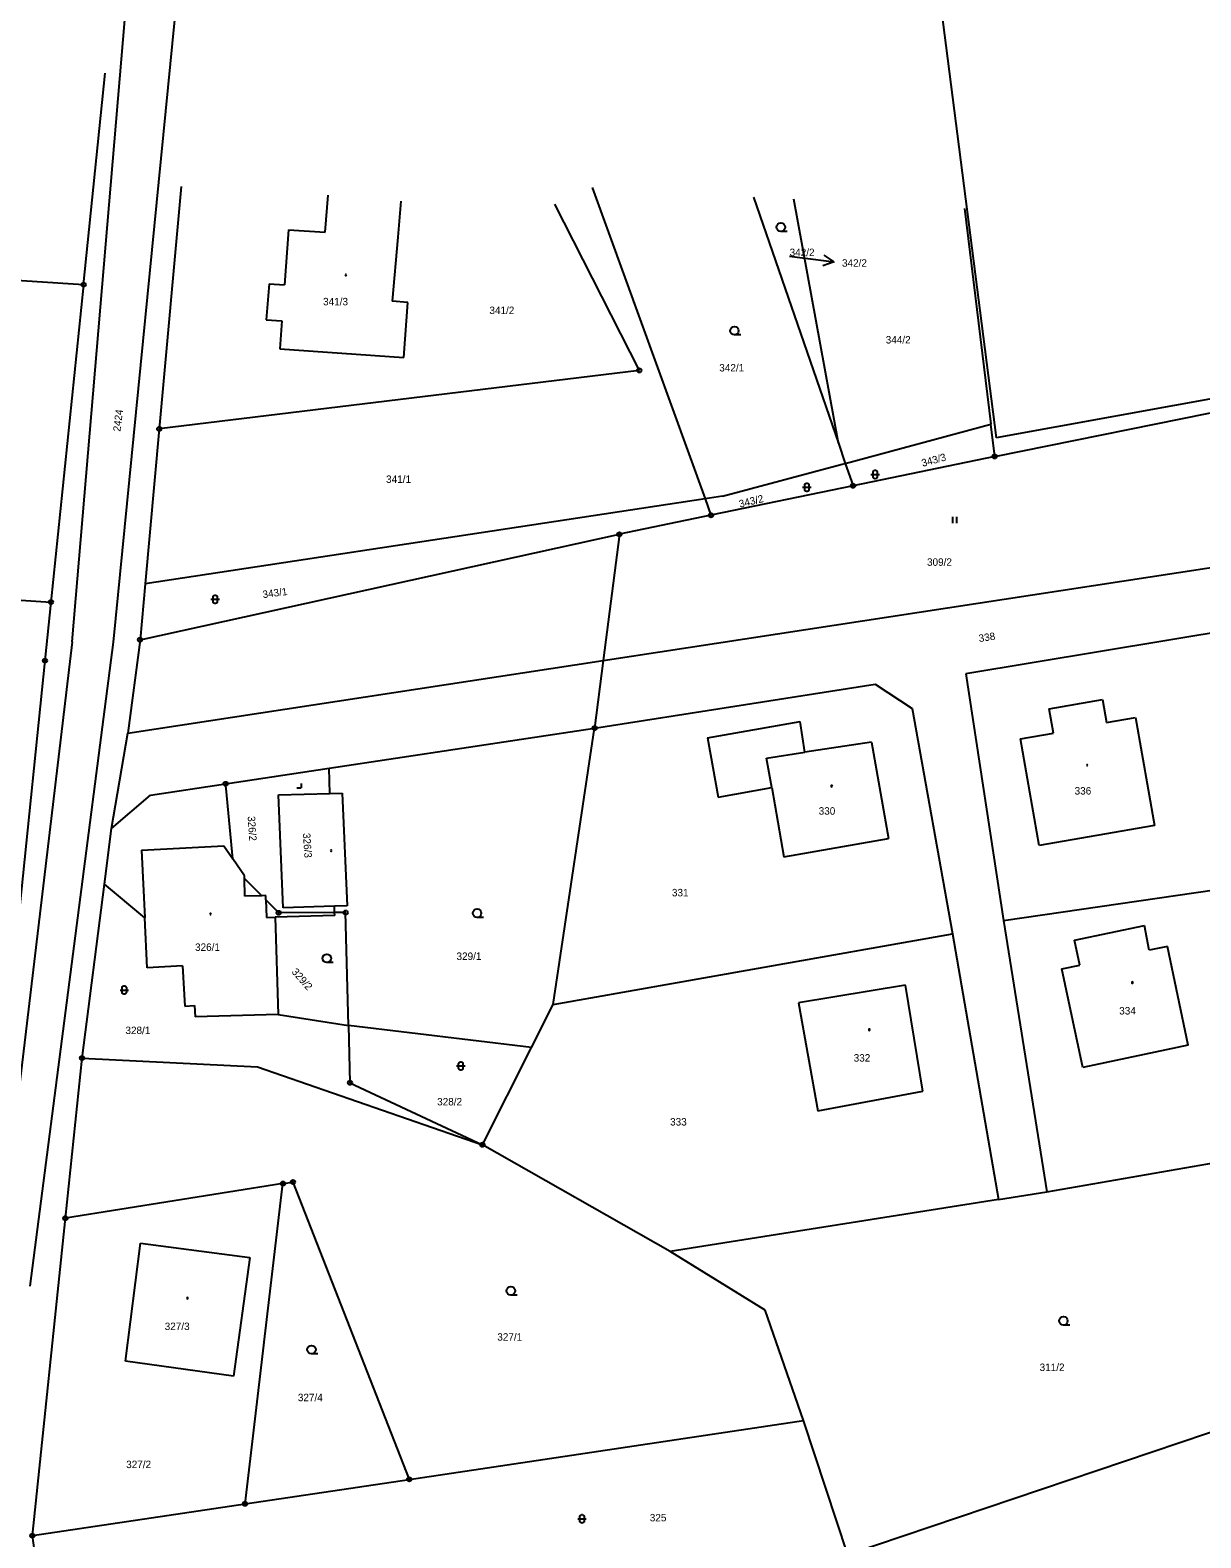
# Model space of a CAD drawing. Extents: x -454285 to -453563, y -1108687 to -1108249.
# Drawn here: x -454136.3 to -454026.3, y -1108463.6 to -1108321.8 of the extents above; entities that cross this region are included whole.
import ezdxf

# ---------------------------------------------------------------- set-up
doc = ezdxf.new("R2010")
doc.units = 0
for name, color, linetype in [('1', 7, 'Continuous'), ('13', 7, 'Continuous'), ('14', 7, 'Continuous'), ('15', 7, 'Continuous'), ('16', 7, 'Continuous'), ('2', 7, 'Continuous'), ('23', 7, 'Continuous'), ('25', 7, 'Continuous'), ('28', 7, 'Continuous')]:
    doc.layers.add(name, color=color, linetype=linetype)

# ---------------------------------------------------------------- blocks, each defined once
blk = doc.blocks.new('Z402')
for start, end in [(0, 180), (180, 0)]:
    blk.add_arc((0, 0), 0.15, start, end)
blk = doc.blocks.new('Z105')
for radius in [0.5, 0.01]:
    blk.add_circle((0, 0), radius)
blk = doc.blocks.new('Z3060')
for p, q in [((-0.5, 1.5), (-0.5, 0)), ((0.5, 1.5), (0.5, 0))]:
    blk.add_line(p, q)
blk = doc.blocks.new('Z3040')
blk.add_line((1.5, 0), (0, 0))
blk.add_circle((0, 1), 1)
blk = doc.blocks.new('Z3160')
for p, q in [((-1, 1), (1, 1)), ((-0.5, 1.6), (-0.4, 1.8)), ((-0.5, 0.4), (-0.5, 1.6)), ((-0.4, 0.2), (-0.5, 0.4)), ((-0.4, 1.8), (-0.3, 1.9)), ((-0.3, 0.1), (-0.4, 0.2)), ((-0.3, 1.9), (-0.1, 2)), ((-0.1, 0), (-0.3, 0.1)), ((-0.1, 2), (0.1, 2)), ((0.1, 0), (-0.1, 0)), ((0.1, 2), (0.3, 1.9)), ((0.3, 0.1), (0.1, 0)), ((0.3, 1.9), (0.4, 1.8)), ((0.4, 0.2), (0.3, 0.1)), ((0.4, 1.8), (0.5, 1.6)), ((0.5, 0.4), (0.4, 0.2)), ((0.5, 1.6), (0.5, 0.4))]:
    blk.add_line(p, q)
blk = doc.blocks.new('Z319')
for p in [(-1, 0), (0, 1)]:
    blk.add_line(p, (0, 0))
blk = doc.blocks.new('Z61')
for p, q in [((0, 3), (-0.5, 2)), ((0, 0), (0, 3)), ((0, 3), (0.5, 2))]:
    blk.add_line(p, q)

msp = doc.modelspace()

# ---------------------------------------------------------------- linework, layer by layer
at = {"layer": '1'}
for p, q in [((-454131.27, -1108345.73), (-454129.23, -1108325.84)), ((-454122.09, -1108336.49), (-454124.17, -1108359.29)), ((-454083.49, -1108336.58), (-454072.88, -1108365.88)), ((-454108.56, -1108340.8), (-454108.3, -1108337.3)), ((-454101.46, -1108337.87), (-454101.75, -1108341.27)), ((-454087.02, -1108338.17), (-454079.06, -1108353.79)), ((-454068.33, -1108337.49), (-454060.35, -1108360.64)), ((-454060.35, -1108360.64), (-454064.54, -1108337.7)), ((-454048.51, -1108338.58), (-454046.03, -1108358.86)), ((-454112.02, -1108340.57), (-454112.4, -1108345.76)), ((-454112.02, -1108340.57), (-454108.56, -1108340.8)), ((-454101.75, -1108341.27), (-454102.27, -1108347.29)), ((-454131.27, -1108345.73), (-454175.21, -1108342.89)), ((-454131.27, -1108345.73), (-454134.34, -1108375.58)), ((-454113.84, -1108345.64), (-454114.11, -1108349.04)), ((-454113.84, -1108345.64), (-454112.4, -1108345.76)), ((-454100.8, -1108347.39), (-454102.27, -1108347.29)), ((-454101.18, -1108352.59), (-454100.8, -1108347.39)), ((-454114.11, -1108349.04), (-454112.64, -1108349.13)), ((-454112.64, -1108349.13), (-454112.83, -1108351.75)), ((-454112.83, -1108351.75), (-454101.18, -1108352.59)), ((-454079.06, -1108353.79), (-454124.17, -1108359.29)), ((-454045.66, -1108361.88), (-454021.54, -1108356.99)), ((-454124.17, -1108359.29), (-454125.49, -1108373.86)), ((-454059.7, -1108362.53), (-454046.03, -1108358.86)), ((-454045.66, -1108361.88), (-454046.03, -1108358.86)), ((-454060.35, -1108360.64), (-454059.7, -1108362.53)), ((-454045.66, -1108361.88), (-454058.97, -1108364.64)), ((-454071.24, -1108365.63), (-454059.99, -1108362.61)), ((-454059.99, -1108362.61), (-454059.7, -1108362.53)), ((-454059.7, -1108362.53), (-454058.97, -1108364.64)), ((-454058.97, -1108364.64), (-454072.32, -1108367.41)), ((-454072.88, -1108365.88), (-454125.49, -1108373.86)), ((-454071.24, -1108365.63), (-454072.88, -1108365.88)), ((-454072.88, -1108365.88), (-454072.32, -1108367.41)), ((-454072.32, -1108367.41), (-454080.93, -1108369.2)), ((-454125.97, -1108379.12), (-454080.93, -1108369.2)), ((-454082.44, -1108381.06), (-454020.21, -1108371.54)), ((-454178.27, -1108372.74), (-454134.34, -1108375.58)), ((-454125.49, -1108373.86), (-454125.97, -1108379.12)), ((-454134.34, -1108375.58), (-454134.9, -1108381.08)), ((-454020.2, -1108377.66), (-454048.37, -1108382.31)), ((-454125.97, -1108379.12), (-454127.13, -1108387.89)), ((-454134.9, -1108381.08), (-454137.27, -1108404.06)), ((-454127.13, -1108387.89), (-454082.44, -1108381.06)), ((-454083.25, -1108387.42), (-454056.88, -1108383.3)), ((-454056.88, -1108383.3), (-454053.42, -1108385.59)), ((-454048.37, -1108382.31), (-454044.83, -1108405.52)), ((-454040.55, -1108385.61), (-454035.53, -1108384.73)), ((-454035.53, -1108384.73), (-454035.15, -1108386.9)), ((-454053.42, -1108385.59), (-454049.63, -1108406.76)), ((-454040.15, -1108387.89), (-454040.55, -1108385.61)), ((-454108.21, -1108391.19), (-454083.25, -1108387.42)), ((-454087.16, -1108413.42), (-454083.25, -1108387.42)), ((-454072.64, -1108388.35), (-454063.94, -1108386.81)), ((-454063.49, -1108389.7), (-454063.94, -1108386.81)), ((-454035.15, -1108386.9), (-454032.42, -1108386.42)), ((-454032.42, -1108386.42), (-454030.64, -1108396.57)), ((-454128.65, -1108396.86), (-454127.13, -1108387.89)), ((-454072.64, -1108388.35), (-454071.65, -1108393.92)), ((-454057.23, -1108388.73), (-454063.49, -1108389.7)), ((-454057.23, -1108388.73), (-454055.63, -1108397.8)), ((-454043.23, -1108388.43), (-454040.15, -1108387.89)), ((-454041.47, -1108398.47), (-454043.23, -1108388.43)), ((-454117.93, -1108392.66), (-454108.21, -1108391.19)), ((-454108.12, -1108393.57), (-454108.21, -1108391.19)), ((-454124.99, -1108393.72), (-454117.93, -1108392.66)), ((-454117.89, -1108393.09), (-454117.93, -1108392.66)), ((-454117.25, -1108399.72), (-454117.89, -1108393.09)), ((-454071.65, -1108393.92), (-454066.61, -1108393.02)), ((-454066.61, -1108393.02), (-454065.46, -1108399.54)), ((-454128.65, -1108396.86), (-454124.99, -1108393.72)), ((-454112.96, -1108393.71), (-454108.12, -1108393.57)), ((-454112.51, -1108404.32), (-454112.96, -1108393.71)), ((-454108.12, -1108393.57), (-454106.96, -1108393.54)), ((-454106.96, -1108393.54), (-454106.52, -1108404.13)), ((-454129.32, -1108402.11), (-454128.65, -1108396.86)), ((-454030.64, -1108396.57), (-454041.47, -1108398.47)), ((-454065.46, -1108399.54), (-454055.63, -1108397.8)), ((-454116.16, -1108401.31), (-454117.25, -1108399.72)), ((-454116.15, -1108401.55), (-454116.16, -1108401.31)), ((-454116.15, -1108401.55), (-454114.53, -1108403.18)), ((-454044.83, -1108405.52), (-454015.47, -1108401.22)), ((-454131.42, -1108418.45), (-454129.32, -1108402.11)), ((-454125.53, -1108405.25), (-454129.32, -1108402.11)), ((-454114.16, -1108403.17), (-454114.53, -1108403.18)), ((-454114.14, -1108403.58), (-454114.16, -1108403.17)), ((-454112.94, -1108404.79), (-454114.14, -1108403.58)), ((-454107.68, -1108404.77), (-454112.94, -1108404.79)), ((-454107.7, -1108404.17), (-454112.51, -1108404.32)), ((-454106.52, -1108404.13), (-454107.7, -1108404.17)), ((-454107.68, -1108404.77), (-454107.7, -1108404.17)), ((-454107.67, -1108405.03), (-454107.68, -1108404.77)), ((-454106.65, -1108404.77), (-454107.68, -1108404.77)), ((-454106.38, -1108415.37), (-454106.65, -1108404.77)), ((-454125.3, -1108409.96), (-454125.53, -1108405.25)), ((-454107.67, -1108405.03), (-454113.26, -1108405.21)), ((-454113.26, -1108405.21), (-454112.99, -1108414.35)), ((-454044.83, -1108405.52), (-454040.76, -1108431.04)), ((-454038.16, -1108407.37), (-454031.59, -1108405.99)), ((-454031.15, -1108408.3), (-454031.59, -1108405.99)), ((-454087.16, -1108413.42), (-454049.63, -1108406.76)), ((-454049.63, -1108406.76), (-454045.29, -1108431.76)), ((-454037.67, -1108409.72), (-454038.16, -1108407.37)), ((-454029.43, -1108407.97), (-454031.15, -1108408.3)), ((-454027.48, -1108417.24), (-454029.43, -1108407.97)), ((-454121.98, -1108409.77), (-454125.3, -1108409.96)), ((-454121.98, -1108409.77), (-454121.76, -1108413.56)), ((-454039.34, -1108410.07), (-454037.67, -1108409.72)), ((-454037.39, -1108419.33), (-454039.34, -1108410.07)), ((-454054.03, -1108411.6), (-454064.09, -1108413.25)), ((-454052.42, -1108421.55), (-454054.03, -1108411.6)), ((-454064.09, -1108413.25), (-454062.28, -1108423.4)), ((-454121.76, -1108413.56), (-454120.85, -1108413.51)), ((-454120.85, -1108413.51), (-454120.79, -1108414.57)), ((-454112.99, -1108414.35), (-454120.79, -1108414.57)), ((-454112.99, -1108414.35), (-454106.38, -1108415.37)), ((-454089.18, -1108417.44), (-454087.16, -1108413.42)), ((-454106.38, -1108415.37), (-454106.24, -1108420.77)), ((-454089.18, -1108417.44), (-454106.38, -1108415.37)), ((-454093.79, -1108426.6), (-454089.18, -1108417.44)), ((-454027.48, -1108417.24), (-454037.39, -1108419.33)), ((-454132.98, -1108433.51), (-454131.42, -1108418.45)), ((-454131.42, -1108418.45), (-454114.93, -1108419.27)), ((-454114.93, -1108419.27), (-454093.79, -1108426.6)), ((-454106.24, -1108420.77), (-454093.79, -1108426.6)), ((-454062.28, -1108423.4), (-454052.42, -1108421.55)), ((-454076.17, -1108436.63), (-454093.79, -1108426.6)), ((-454040.76, -1108431.04), (-454024.91, -1108428.28)), ((-454112.54, -1108430.25), (-454132.98, -1108433.51)), ((-454116.1, -1108460.36), (-454112.54, -1108430.25)), ((-454112.54, -1108430.25), (-454111.6, -1108430.1)), ((-454111.6, -1108430.1), (-454100.67, -1108458.06)), ((-454045.29, -1108431.76), (-454076.17, -1108436.63)), ((-454045.29, -1108431.76), (-454040.76, -1108431.04)), ((-454136.08, -1108463.35), (-454132.98, -1108433.51)), ((-454127.34, -1108446.96), (-454125.91, -1108435.85)), ((-454125.91, -1108435.85), (-454115.66, -1108437.2)), ((-454115.66, -1108437.2), (-454117.18, -1108448.35)), ((-454067.24, -1108442.15), (-454076.17, -1108436.63)), ((-454063.62, -1108452.52), (-454067.24, -1108442.15)), ((-454117.18, -1108448.35), (-454127.34, -1108446.96)), ((-454100.67, -1108458.06), (-454063.62, -1108452.52)), ((-454059.47, -1108465.16), (-454063.62, -1108452.52)), ((-454019.82, -1108451.78), (-454059.47, -1108465.16)), ((-454116.1, -1108460.36), (-454100.67, -1108458.06)), ((-454136.08, -1108463.35), (-454116.1, -1108460.36)), ((-454135.23, -1108469.28), (-454136.08, -1108463.35))]:
    msp.add_line(p, q, dxfattribs=at)
at = {"layer": '13'}
msp.add_line((-454064.93, -1108343.04), (-454063.73, -1108343.2), dxfattribs=at)
at = {"layer": '2'}
for p, q in [((-454132.33, -1108379.3), (-454121.34, -1108249.13)), ((-454119.73, -1108290.27), (-454128.49, -1108379.34)), ((-454054.06, -1108293.59), (-454045.52, -1108360.12)), ((-454008.01, -1108353.31), (-454045.52, -1108360.12)), ((-454080.93, -1108369.2), (-454082.44, -1108381.06)), ((-454132.33, -1108379.3), (-454139.45, -1108438.88)), ((-454128.49, -1108379.34), (-454136.31, -1108439.89)), ((-454082.44, -1108381.06), (-454083.25, -1108387.42)), ((-454067.1, -1108390.25), (-454063.49, -1108389.7)), ((-454066.61, -1108393.02), (-454067.1, -1108390.25)), ((-454125.83, -1108398.91), (-454118.09, -1108398.5)), ((-454125.83, -1108398.91), (-454125.53, -1108405.25)), ((-454118.09, -1108398.5), (-454117.25, -1108399.72)), ((-454116.11, -1108403.23), (-454116.15, -1108401.55)), ((-454114.53, -1108403.18), (-454116.11, -1108403.23)), ((-454114.14, -1108403.58), (-454114.07, -1108405.24)), ((-454114.07, -1108405.24), (-454113.26, -1108405.21))]:
    msp.add_line(p, q, dxfattribs=at)

# ---------------------------------------------------------------- block references
at = {"layer": '16', "rotation": -97.59460000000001}
msp.add_blockref('Z61', (-454063.73, -1108343.2), dxfattribs=at)
at = {"layer": '23', "xscale": 0.4, "yscale": 0.4000000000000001}
for name, p in [('Z3040', (-454065.76, -1108340.72)), ('Z3040', (-454070.12, -1108350.46)), ('Z3160', (-454056.89, -1108363.97)), ('Z3160', (-454063.31, -1108365.18)), ('Z3060', (-454049.44, -1108368.15)), ('Z3160', (-454118.91, -1108375.71)), ('Z319', (-454110.83, -1108393.03)), ('Z3040', (-454094.3, -1108405.22)), ('Z3040', (-454108.41, -1108409.47)), ('Z3160', (-454127.45, -1108412.45)), ('Z3160', (-454095.83, -1108419.59)), ('Z3040', (-454091.12, -1108440.74)), ('Z3040', (-454039.21, -1108443.56)), ('Z3040', (-454109.85, -1108446.26)), ('Z3160', (-454084.44, -1108462.17))]:
    msp.add_blockref(name, p, dxfattribs=at)
at = {"layer": '25', "xscale": 0.4, "yscale": 0.4000000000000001}
for p in [(-454106.63, -1108344.81), (-454036.97, -1108390.91), (-454060.97, -1108392.87), (-454108.01, -1108398.94), (-454119.35, -1108404.91), (-454032.73, -1108411.35), (-454057.43, -1108415.78), (-454121.53, -1108441.02)]:
    msp.add_blockref('Z402', p, dxfattribs=at)
at = {"layer": '28', "xscale": 0.4, "yscale": 0.4000000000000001}
for p in [(-454131.27, -1108345.73), (-454079.06, -1108353.79), (-454124.17, -1108359.29), (-454045.66, -1108361.88), (-454058.97, -1108364.64), (-454072.32, -1108367.41), (-454080.93, -1108369.2), (-454134.34, -1108375.58), (-454125.97, -1108379.12), (-454134.9, -1108381.08), (-454083.25, -1108387.42), (-454117.93, -1108392.66), (-454112.94, -1108404.79), (-454106.65, -1108404.77), (-454131.42, -1108418.45), (-454106.24, -1108420.77), (-454093.79, -1108426.6), (-454112.54, -1108430.25), (-454111.6, -1108430.1), (-454132.98, -1108433.51), (-454100.67, -1108458.06), (-454116.1, -1108460.36), (-454136.08, -1108463.35)]:
    msp.add_blockref('Z105', p, dxfattribs=at)

# ---------------------------------------------------------------- texts
at = {"layer": '14'}
for s, p in [('342/2', (-454064.93, -1108343.04)), ('341/2', (-454093.14, -1108348.49)), ('344/2', (-454055.9, -1108351.26)), ('342/1', (-454071.54, -1108353.89)), ('341/1', (-454102.85, -1108364.37)), ('309/2', (-454052.02, -1108372.16)), ('331', (-454075.99, -1108403.24)), ('329/1', (-454096.23, -1108409.22)), ('328/1', (-454127.34, -1108416.19)), ('328/2', (-454098.05, -1108422.9)), ('333', (-454076.16, -1108424.79)), ('327/1', (-454092.4, -1108445.02)), ('311/2', (-454041.44, -1108447.87)), ('327/4', (-454111.14, -1108450.71)), ('327/2', (-454127.27, -1108457)), ('325', (-454078.07, -1108462.01))]:
    msp.add_text(s, height=0.7, dxfattribs=at).set_placement(p)
for s, rotation, p in [('2424', 82.854, (-454127.82, -1108359.57)), ('343/3', 15.3, (-454052.43, -1108362.86)), ('343/2', 13.5, (-454069.6, -1108366.7)), ('343/1', 7.623, (-454114.41, -1108375.21)), ('338', 8.82, (-454047.11, -1108379.34)), ('329/2', 311.112, (-454111.77, -1108410.37))]:
    msp.add_text(s, height=0.7, rotation=rotation, dxfattribs=at).set_placement(p)
at = {"layer": '15'}
for s, p in [('341/3', (-454108.77, -1108347.67)), ('336', (-454038.15, -1108393.67)), ('330', (-454062.2, -1108395.56)), ('326/1', (-454120.8, -1108408.37)), ('334', (-454033.96, -1108414.35)), ('332', (-454058.91, -1108418.78)), ('327/3', (-454123.65, -1108444.02))]:
    msp.add_text(s, height=0.7, dxfattribs=at).set_placement(p)
for s, p in [('326/2', (-454115.86, -1108395.72)), ('326/3', (-454110.67, -1108397.31))]:
    msp.add_text(s, height=0.7, rotation=273.933, dxfattribs=at).set_placement(p)
at = {"layer": '16'}
msp.add_text('342/2', height=0.7, dxfattribs=at).set_placement((-454060.01, -1108344.04))

doc.saveas('drawing.dxf')
